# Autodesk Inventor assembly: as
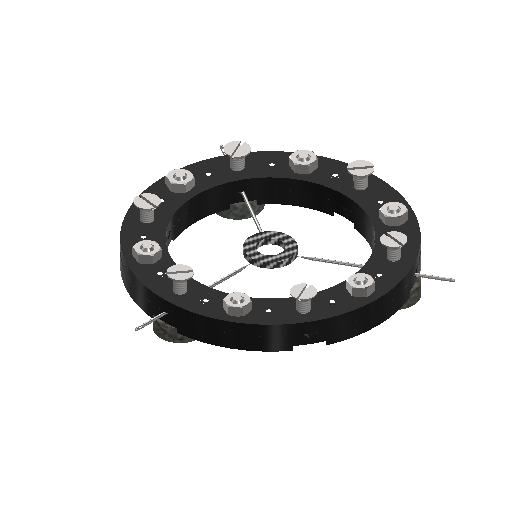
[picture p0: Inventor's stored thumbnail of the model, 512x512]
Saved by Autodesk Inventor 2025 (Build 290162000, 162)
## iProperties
Created: 2025-01
Part Number: as
Document SubType Name: Assembly
Designer: dansp
Author: dansp
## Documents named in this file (10)
- C:\Users\dansp\Desktop\Model\Model\SESTAVA.iam
- C:\Users\dansp\Desktop\Model\Model\HORNI_CAST.ipt
- C:\Users\dansp\Desktop\Model\Model\MAGNET.ipt
- C:\Users\dansp\Desktop\Model\Model\UPINACI_PRVEK.ipt
- C:\Users\dansp\Desktop\Model\Model\SPODNI_CAST.ipt
- C:\Users\dansp\Desktop\Model\Model\SROUB_SPOJ.ipt
- C:\Users\dansp\Desktop\Model\Model\MATICE_SPOJ.ipt
- C:\Users\dansp\Desktop\Model\Model\SROUB.ipt
- C:\Users\dansp\Desktop\Model\Model\TESNENI.ipt
- C:\Users\dansp\Desktop\Model\Model\delete.iam
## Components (57 placed, 9 different names)
1. HORNI_CAST:1 — Mate:1, Flush:1, Mate:2, Flush:2, Tangent:1, Tangent:2, Mate:4, Mate:5, Mate:7, Mate:8, Mate:9, Mate:14, Mate:15, Mate:16, Mate:17, Mate:20, Mate:21
2. SPODNI_CAST:1 — Mate:4, Mate:5, Mate:6, Mate:11, Mate:12, Mate:13, Mate:22
3. TESNENI:1 — Mate:14, Mate:15
4. UPINACI_PRVEK:1 — Tangent:1, Tangent:2
5. UPINACI_PRVEK:2
6. UPINACI_PRVEK:3
7. MAGNET:1 — Flush:2, Mate:7, Mate:18, Mate:19
8. MAGNET:2
9. MAGNET:3
10. SROUB_SPOJ:1 — Mate:8, Mate:9, Mate:10
11. MATICE_SPOJ:1 — Mate:10, Mate:11
12. SROUB_SPOJ:2
13. MATICE_SPOJ:2
14. SROUB_SPOJ:3
15. MATICE_SPOJ:3
16. SROUB_SPOJ:4
17. MATICE_SPOJ:4
18. SROUB_SPOJ:5
19. MATICE_SPOJ:5
20. SROUB_SPOJ:6
21. MATICE_SPOJ:6
22. SROUB:1 — Mate:12, Mate:13
23. SROUB:2
24. SROUB:3
25. SROUB:4
26. SROUB:5
27. SROUB:6
28. delete:1 [sub-assembly] — Mate:16, Mate:17
29. delete:2 [sub-assembly]
30. delete:3 [sub-assembly]
31. delete:4 [sub-assembly] — Mate:18, Mate:19
32. delete:5 [sub-assembly]
33. delete:6 [sub-assembly]
34. delete:7 [sub-assembly] — Mate:21
35. delete:8 [sub-assembly] — Mate:20
36. delete:9 [sub-assembly]
37. delete:10 [sub-assembly]
38. delete:11 [sub-assembly]
39. delete:12 [sub-assembly]
40. delete:13 [sub-assembly]
41. delete:14 [sub-assembly]
42. delete:15 [sub-assembly]
43. delete:16 [sub-assembly]
44. delete:17 [sub-assembly]
45. delete:18 [sub-assembly]
46. delete:19 [sub-assembly] — Mate:22
47. delete:20 [sub-assembly]
48. delete:21 [sub-assembly]
49. delete:22 [sub-assembly]
50. delete:23 [sub-assembly]
51. delete:24 [sub-assembly]
52. delete:25 [sub-assembly]
53. delete:26 [sub-assembly]
54. delete:27 [sub-assembly]
55. delete:28 [sub-assembly]
56. delete:29 [sub-assembly]
57. delete:30 [sub-assembly]
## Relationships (25: Mate 21, Flush 2, Tangent 2)
- Mate:1: HORNI_CAST:1
- Flush:1: HORNI_CAST:1
- Mate:2: HORNI_CAST:1
- Flush:2: HORNI_CAST:1 ↔ MAGNET:1
- Tangent:1: HORNI_CAST:1 ↔ UPINACI_PRVEK:1
- Tangent:2: HORNI_CAST:1 ↔ UPINACI_PRVEK:1
- Mate:4: HORNI_CAST:1 ↔ SPODNI_CAST:1
- Mate:5: HORNI_CAST:1 ↔ SPODNI_CAST:1
- Mate:6: SPODNI_CAST:1
- Mate:7: HORNI_CAST:1 ↔ MAGNET:1
- Mate:8: HORNI_CAST:1 ↔ SROUB_SPOJ:1
- Mate:9: HORNI_CAST:1 ↔ SROUB_SPOJ:1
- Mate:10: SROUB_SPOJ:1 ↔ MATICE_SPOJ:1
- Mate:11: SPODNI_CAST:1 ↔ MATICE_SPOJ:1
- Mate:12: SPODNI_CAST:1 ↔ SROUB:1
- Mate:13: SPODNI_CAST:1 ↔ SROUB:1
- Mate:14: HORNI_CAST:1 ↔ TESNENI:1
- Mate:15: HORNI_CAST:1 ↔ TESNENI:1
- Mate:16: HORNI_CAST:1 ↔ delete:1
- Mate:17: HORNI_CAST:1 ↔ delete:1
- Mate:18: MAGNET:1 ↔ delete:4
- Mate:19: MAGNET:1 ↔ delete:4
- Mate:20: HORNI_CAST:1 ↔ delete:8
- Mate:21: HORNI_CAST:1 ↔ delete:7
- Mate:22: SPODNI_CAST:1 ↔ delete:19
